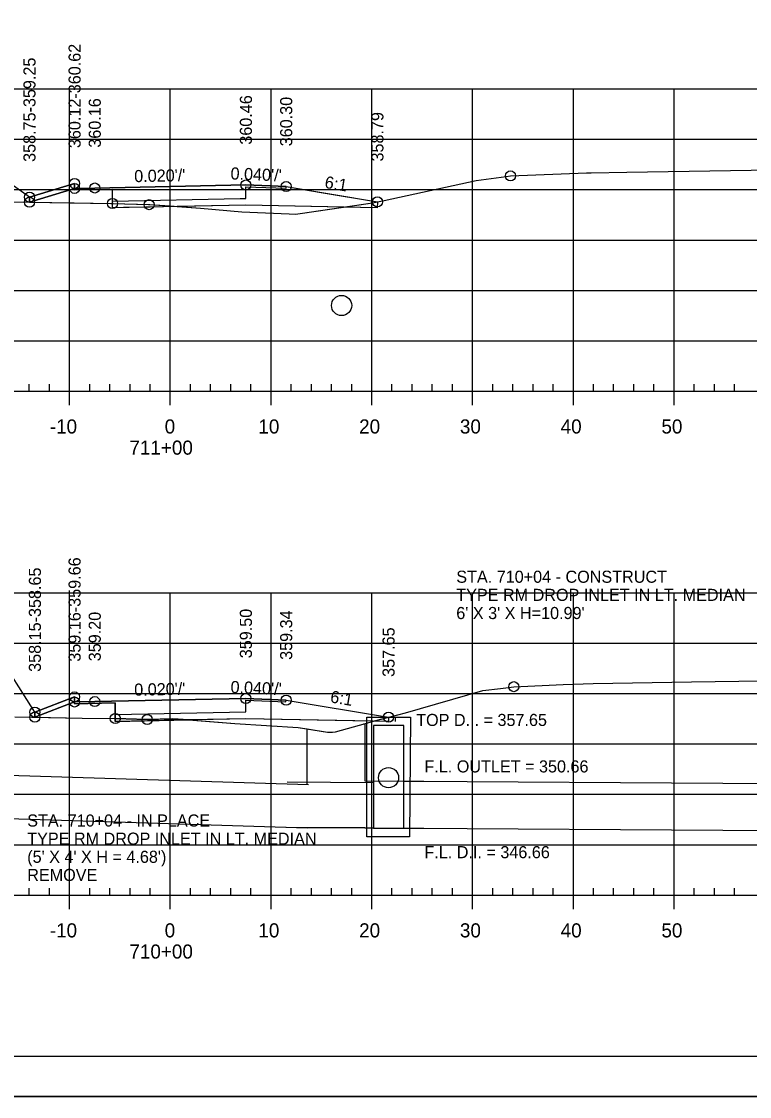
# Model space of a CAD drawing. Extents: x 1359801 to 1362404, y 372415 to 374228.
# Drawn here: x 1361188.9 to 1361261.2, y 373374.6 to 373481.3 of the extents above; entities that cross this region are included whole.
import ezdxf

# ---------------------------------------------------------------- set-up
doc = ezdxf.new("R2010")
doc.units = 0
for name, color, linetype in [('Default', 7, 'Continuous'), ('S_DRG_PT_SYM', 7, 'Continuous'), ('S_ELECTRIC_UTILITIES_ANNOT', 7, 'Continuous'), ('S_IRON_PIN', 7, 'Continuous'), ('S_MAILBOX', 7, 'Continuous'), ('S_PRIMARY_CTL', 7, 'Continuous'), ('S_SANITARY_SEWER', 7, 'Continuous'), ('S_SHOULDER', 7, 'Continuous'), ('S_TELEPHONE_UTILITIES_ANNOT', 7, 'Continuous'), ('S_UNDERGROUND_CABLE', 7, 'Continuous'), ('S_UTILITY_POLE_ANNOT', 7, 'Continuous'), ('S_UTL_PT_SYM', 7, 'Continuous'), ('S_WATER_UTILITIES', 7, 'Continuous')]:
    doc.layers.add(name, color=color, linetype=linetype)

msp = doc.modelspace()

# ---------------------------------------------------------------- linework, layer by layer
at = {"layer": 'Default'}
for points in [[(1361196.21, 373464.76), (1361194.21, 373464.72), (1361194.21, 373465.22), (1361189.73, 373463.85), (1361189.73, 373463.35)], [(1361196.21, 373413.8), (1361194.21, 373413.76), (1361194.21, 373414.26), (1361190.27, 373412.75), (1361190.27, 373412.25)]]:
    msp.add_lwpolyline(points, dxfattribs=at)
at = {"layer": 'S_DRG_PT_SYM'}
for points in [[(1361187.73, 373463.38), (1361197.79, 373463.23), (1361197.97, 373463.23), (1361201.56, 373463.11), (1361201.6, 373463.11), (1361201.67, 373463.11), (1361203.66, 373462.98), (1361206.69, 373462.75), (1361210.8, 373462.41), (1361215.49, 373462.19), (1361216.14, 373462.16), (1361216.61, 373462.23), (1361223.76, 373463.29), (1361224.92, 373463.53), (1361234.05, 373465.49), (1361237.05, 373465.9), (1361237.47, 373465.96), (1361245.01, 373466.27), (1361245.47, 373466.28), (1361249.03, 373466.33), (1361271.64, 373466.69)], [(1361188.27, 373412.28), (1361194.97, 373412.17), (1361198.25, 373412.12), (1361199.34, 373412.09), (1361201.42, 373412.02), (1361203.71, 373412.09), (1361203.97, 373412.1), (1361204.81, 373412.04), (1361210.1, 373411.64), (1361216.4, 373411.23), (1361219.31, 373410.78), (1361219.82, 373410.75), (1361220.09, 373410.81), (1361223.08, 373411.64), (1361224.01, 373411.89), (1361227.06, 373412.69), (1361234.73, 373414.91), (1361236.49, 373415.11), (1361237.79, 373415.28), (1361242.7, 373415.48), (1361245.66, 373415.6), (1361255.44, 373415.75), (1361271.89, 373415.98)]]:
    msp.add_lwpolyline(points, dxfattribs=at)
at = {"layer": 'S_ELECTRIC_UTILITIES_ANNOT'}
for p, q in [((1361189.73, 373463.35), (1361194.21, 373464.72)), ((1361194.21, 373464.72), (1361189.73, 373463.35)), ((1361189.73, 373463.35), (1361194.17, 373463.28)), ((1361197.98, 373463.3), (1361197.96, 373463.3)), ((1361194.21, 373413.59), (1361194.21, 373413.59)), ((1361198.25, 373412.12), (1361198.24, 373412.34)), ((1361198.25, 373412.12), (1361198.24, 373412.34)), ((1361211.21, 373412.1), (1361211.21, 373412.1)), ((1361223.84, 373411.85), (1361223.84, 373411.85)), ((1361223.84, 373411.85), (1361223.84, 373411.85)), ((1361223.84, 373411.85), (1361223.84, 373411.85)), ((1361223.84, 373411.85), (1361223.84, 373411.85))]:
    msp.add_line(p, q, dxfattribs=at)
for points in [[(1361194.17, 373463.28), (1361197.97, 373463.23), (1361197.97, 373464.62), (1361194.21, 373464.55), (1361194.21, 373464.72)], [(1361197.96, 373463.3), (1361197.97, 373463.23), (1361197.98, 373463.22)], [(1361220.9, 373462.87), (1361211.21, 373463.06), (1361204.4, 373462.92)], [(1361204.4, 373462.92), (1361206.69, 373462.75), (1361210.8, 373462.41), (1361215.49, 373462.19), (1361216.14, 373462.16), (1361216.61, 373462.23), (1361220.9, 373462.87)], [(1361190.27, 373412.25), (1361194.21, 373413.76), (1361194.21, 373413.59)], [(1361194.21, 373413.59), (1361194.21, 373413.76), (1361190.27, 373412.25)], [(1361198.24, 373412.34), (1361198.25, 373413.67), (1361194.21, 373413.59)], [(1361190.27, 373412.25), (1361194.97, 373412.17), (1361198.25, 373412.12)], [(1361211.21, 373412.1), (1361205.52, 373411.99), (1361210.1, 373411.64), (1361216.4, 373411.23), (1361217.28, 373411.1), (1361219.31, 373410.78), (1361219.82, 373410.75), (1361220.09, 373410.81), (1361223.08, 373411.64), (1361223.2, 373411.67), (1361223.84, 373411.85)], [(1361223.84, 373411.85), (1361211.21, 373412.1)], [(1361223.84, 373411.85), (1361223.84, 373411.85), (1361223.84, 373411.85)], [(1361223.84, 373411.85), (1361223.84, 373411.85), (1361223.84, 373411.85)]]:
    msp.add_lwpolyline(points, dxfattribs=at)
for points in [[(1361197.98, 373462.8), (1361197.97, 373463.23), (1361201.67, 373463.11), (1361204.4, 373462.92), (1361201.71, 373462.87), (1361199.05, 373462.82)], [(1361220.9, 373462.87), (1361223.76, 373463.29), (1361224.26, 373463.39), (1361224.25, 373462.8)], [(1361198.25, 373412.12), (1361198.25, 373411.84), (1361205.52, 373411.99), (1361203.97, 373412.1), (1361201.42, 373412.02)], [(1361223.84, 373411.85), (1361225.37, 373412.25), (1361225.37, 373411.83)]]:
    msp.add_lwpolyline(points, close=True, dxfattribs=at)
at = {"layer": 'S_MAILBOX'}
for p, q in [((1361058.71, 373474.6), (1361348.71, 373474.6)), ((1361058.71, 373474.6), (1361348.71, 373474.6)), ((1361193.71, 373444.6), (1361193.71, 373474.6)), ((1361193.71, 373444.6), (1361193.71, 373474.6)), ((1361203.71, 373444.6), (1361203.71, 373474.6)), ((1361203.71, 373444.6), (1361203.71, 373474.6)), ((1361213.71, 373444.6), (1361213.71, 373474.6)), ((1361213.71, 373444.6), (1361213.71, 373474.6)), ((1361223.71, 373444.6), (1361223.71, 373474.6)), ((1361223.71, 373444.6), (1361223.71, 373474.6)), ((1361233.71, 373444.6), (1361233.71, 373474.6)), ((1361233.71, 373444.6), (1361233.71, 373474.6)), ((1361243.71, 373444.6), (1361243.71, 373474.6)), ((1361243.71, 373444.6), (1361243.71, 373474.6)), ((1361253.71, 373444.6), (1361253.71, 373474.6)), ((1361253.71, 373444.6), (1361253.71, 373474.6)), ((1361058.71, 373469.6), (1361348.71, 373469.6)), ((1361058.71, 373469.6), (1361348.71, 373469.6)), ((1361058.71, 373464.6), (1361348.71, 373464.6)), ((1361058.71, 373464.6), (1361348.71, 373464.6)), ((1361058.71, 373459.6), (1361348.71, 373459.6)), ((1361058.71, 373459.6), (1361348.71, 373459.6)), ((1361058.71, 373454.6), (1361348.71, 373454.6)), ((1361058.71, 373454.6), (1361348.71, 373454.6)), ((1361058.71, 373449.6), (1361348.71, 373449.6)), ((1361058.71, 373449.6), (1361348.71, 373449.6)), ((1361058.71, 373444.6), (1361348.71, 373444.6)), ((1361058.71, 373444.6), (1361348.71, 373444.6)), ((1361058.71, 373424.6), (1361348.71, 373424.6)), ((1361193.71, 373394.6), (1361193.71, 373424.6)), ((1361203.71, 373394.6), (1361203.71, 373424.6)), ((1361213.71, 373394.6), (1361213.71, 373424.6)), ((1361223.71, 373394.6), (1361223.71, 373424.6)), ((1361233.71, 373394.6), (1361233.71, 373424.6)), ((1361243.71, 373394.6), (1361243.71, 373424.6)), ((1361253.71, 373394.6), (1361253.71, 373424.6)), ((1361058.71, 373419.6), (1361348.71, 373419.6)), ((1361058.71, 373414.6), (1361348.71, 373414.6)), ((1361058.71, 373409.6), (1361348.71, 373409.6)), ((1361058.71, 373404.6), (1361348.71, 373404.6)), ((1361058.71, 373399.6), (1361348.71, 373399.6)), ((1361058.71, 373394.6), (1361348.71, 373394.6))]:
    msp.add_line(p, q, dxfattribs=at)
at = {"layer": 'S_SANITARY_SEWER'}
for points in [[(1361189.73, 373463.35), (1361189.73, 373463.85), (1361194.21, 373465.22), (1361194.21, 373464.72), (1361196.21, 373464.76), (1361211.19, 373465.06), (1361211.21, 373465.06), (1361215.21, 373464.9), (1361215.21, 373464.9), (1361215.22, 373464.9), (1361218.67, 373464.32), (1361224.26, 373463.39)], [(1361215.21, 373464.9), (1361211.21, 373465.06), (1361196.21, 373464.76)], [(1361190.27, 373412.25), (1361190.27, 373412.75), (1361194.21, 373414.26), (1361194.21, 373413.76), (1361196.21, 373413.8), (1361211.21, 373414.1), (1361215.21, 373413.94), (1361225.37, 373412.25)], [(1361215.21, 373413.94), (1361211.21, 373414.1), (1361196.21, 373413.8)]]:
    msp.add_lwpolyline(points, dxfattribs=at)
at = {"layer": 'S_SHOULDER'}
for p, q in [((1361225.37, 373412.25), (1361225.37, 373411.83)), ((1361225.37, 373411.83), (1361225.37, 373411.82)), ((1361226.03, 373412.25), (1361226.03, 373411.83)), ((1361033.31, 373374.62), (1361366.64, 373374.62))]:
    msp.add_line(p, q, dxfattribs=at)
for points in [[(1361033.3, 373587.95), (1361366.64, 373587.95), (1361366.64, 373374.61), (1361033.3, 373374.61)], [(1361279.63, 373584.06), (1361279.63, 373574.18), (1361315.36, 373574.18), (1361315.36, 373571.26), (1361338.56, 373571.26), (1361338.56, 373546.93), (1361361.89, 373546.93), (1361361.89, 373378.6), (1361045.71, 373378.6), (1361045.71, 373584.06)]]:
    msp.add_lwpolyline(points, close=True, dxfattribs=at)
for points in [[(1361197.98, 373463.46), (1361210.63, 373463.71), (1361211.21, 373463.73), (1361211.19, 373464.89)], [(1361211.19, 373464.89), (1361211.21, 373464.89), (1361215.19, 373464.73), (1361215.21, 373464.73)], [(1361215.21, 373464.73), (1361215.21, 373464.9), (1361224.26, 373463.39)], [(1361224.26, 373463.39), (1361224.25, 373462.8), (1361211.21, 373463.06), (1361197.98, 373462.8), (1361197.98, 373463.46)], [(1361198.25, 373412.51), (1361211.21, 373412.77), (1361211.21, 373413.93)], [(1361211.21, 373413.93), (1361215.19, 373413.77), (1361215.21, 373413.94), (1361225.37, 373412.25)], [(1361225.37, 373411.82), (1361211.21, 373412.1), (1361198.25, 373411.84), (1361198.25, 373412.51)]]:
    msp.add_lwpolyline(points, dxfattribs=at)
for centre in [(1361194.21, 373465.22), (1361237.47, 373465.96), (1361194.21, 373464.72), (1361196.21, 373464.76), (1361211.21, 373465.06), (1361215.21, 373464.9), (1361189.73, 373463.85), (1361189.73, 373463.35), (1361197.97, 373463.23), (1361201.6, 373463.11), (1361224.26, 373463.39), (1361237.79, 373415.28), (1361194.21, 373414.26), (1361211.21, 373414.1), (1361215.21, 373413.94), (1361194.21, 373413.76), (1361196.21, 373413.8), (1361190.27, 373412.75), (1361190.27, 373412.25), (1361198.25, 373412.12), (1361201.42, 373412.02), (1361225.37, 373412.25)]:
    msp.add_circle(centre, 0.5, dxfattribs=at)
at = {"layer": 'S_TELEPHONE_UTILITIES_ANNOT'}
for points in [[(1361189.73, 373463.85), (1361180.91, 373470.08), (1361180.91, 373470.08), (1361179.05, 373470.08)], [(1361190.27, 373412.75), (1361178.82, 373430.82), (1361178.82, 373430.82), (1361173.45, 373430.82)]]:
    msp.add_lwpolyline(points, dxfattribs=at)
at = {"layer": 'S_UNDERGROUND_CABLE'}
msp.add_line((1361225.37, 373412.25), (1361225.37, 373411.83), dxfattribs=at)
for points in [[(1361224.26, 373463.39), (1361224.25, 373462.8), (1361211.21, 373463.06), (1361197.98, 373462.8), (1361197.97, 373464.62), (1361194.21, 373464.55), (1361194.21, 373464.72), (1361194.21, 373464.72)], [(1361194.21, 373413.59), (1361198.25, 373413.67), (1361198.25, 373411.84)], [(1361225.37, 373411.82), (1361211.21, 373412.1), (1361198.25, 373411.84), (1361198.25, 373413.67), (1361194.21, 373413.59)]]:
    msp.add_lwpolyline(points, dxfattribs=at)
at = {"layer": 'S_UTILITY_POLE_ANNOT'}
for p, q in [((1361224.52, 373412.25), (1361227.52, 373412.25)), ((1361163.02, 373407.25), (1361217.42, 373405.58)), ((1361223.03, 373405.95), (1361348.74, 373405.14)), ((1361215.32, 373405.84), (1361223.9, 373405.77)), ((1361162.89, 373402.95), (1361217.28, 373401.28)), ((1361215.29, 373401.34), (1361223.87, 373401.27)), ((1361223, 373401.28), (1361348.71, 373400.47)), ((1361226.87, 373401.25), (1361228.87, 373401.24))]:
    msp.add_line(p, q, dxfattribs=at)
for points in [[(1361223, 373411.59), (1361223, 373405.95)], [(1361217.28, 373405.58), (1361217.28, 373411.1)], [(1361226.87, 373405.92), (1361226.87, 373405.92), (1361228.87, 373405.91)], [(1361223, 373401.28), (1361217.28, 373401.28)]]:
    msp.add_lwpolyline(points, dxfattribs=at)
for points in [[(1361223.2, 373412.25), (1361227.54, 373412.25), (1361227.54, 373412.25), (1361227.46, 373400.38), (1361223.2, 373400.38)], [(1361223.87, 373411.42), (1361223.87, 373401.25), (1361226.87, 373401.25), (1361226.87, 373411.42)]]:
    msp.add_lwpolyline(points, close=True, dxfattribs=at)
for centre in [(1361220.71, 373453.1), (1361225.37, 373406.25)]:
    msp.add_circle(centre, 1, dxfattribs=at)
at = {"layer": 'S_UTL_PT_SYM'}
msp.add_line((1361361.89, 373378.6), (1361045.71, 373378.6), dxfattribs=at)
at = {"layer": 'S_WATER_UTILITIES'}
for p, q in [((1361058.71, 373444.6), (1361348.71, 373444.6)), ((1361189.71, 373444.6), (1361189.71, 373445.3)), ((1361191.71, 373444.6), (1361191.71, 373445.3)), ((1361193.71, 373443.2), (1361193.71, 373444.6)), ((1361195.71, 373444.6), (1361195.71, 373445.3)), ((1361197.71, 373444.6), (1361197.71, 373445.3)), ((1361199.71, 373444.6), (1361199.71, 373445.3)), ((1361201.71, 373444.6), (1361201.71, 373445.3)), ((1361203.71, 373443.2), (1361203.71, 373444.6)), ((1361205.71, 373444.6), (1361205.71, 373445.3)), ((1361207.71, 373444.6), (1361207.71, 373445.3)), ((1361209.71, 373444.6), (1361209.71, 373445.3)), ((1361211.71, 373444.6), (1361211.71, 373445.3)), ((1361213.71, 373443.2), (1361213.71, 373444.6)), ((1361215.71, 373444.6), (1361215.71, 373445.3)), ((1361217.71, 373444.6), (1361217.71, 373445.3)), ((1361219.71, 373444.6), (1361219.71, 373445.3)), ((1361221.71, 373444.6), (1361221.71, 373445.3)), ((1361223.71, 373443.2), (1361223.71, 373444.6)), ((1361225.71, 373444.6), (1361225.71, 373445.3)), ((1361227.71, 373444.6), (1361227.71, 373445.3)), ((1361229.71, 373444.6), (1361229.71, 373445.3)), ((1361231.71, 373444.6), (1361231.71, 373445.3)), ((1361233.71, 373443.2), (1361233.71, 373444.6)), ((1361235.71, 373444.6), (1361235.71, 373445.3)), ((1361237.71, 373444.6), (1361237.71, 373445.3)), ((1361239.71, 373444.6), (1361239.71, 373445.3)), ((1361241.71, 373444.6), (1361241.71, 373445.3)), ((1361243.71, 373443.2), (1361243.71, 373444.6)), ((1361245.71, 373444.6), (1361245.71, 373445.3)), ((1361247.71, 373444.6), (1361247.71, 373445.3)), ((1361249.71, 373444.6), (1361249.71, 373445.3)), ((1361251.71, 373444.6), (1361251.71, 373445.3)), ((1361253.71, 373443.2), (1361253.71, 373444.6)), ((1361255.71, 373444.6), (1361255.71, 373445.3)), ((1361257.71, 373444.6), (1361257.71, 373445.3)), ((1361259.71, 373444.6), (1361259.71, 373445.3)), ((1361189.71, 373394.6), (1361189.71, 373395.3)), ((1361191.71, 373394.6), (1361191.71, 373395.3)), ((1361195.71, 373394.6), (1361195.71, 373395.3)), ((1361197.71, 373394.6), (1361197.71, 373395.3)), ((1361199.71, 373394.6), (1361199.71, 373395.3)), ((1361201.71, 373394.6), (1361201.71, 373395.3)), ((1361205.71, 373394.6), (1361205.71, 373395.3)), ((1361207.71, 373394.6), (1361207.71, 373395.3)), ((1361209.71, 373394.6), (1361209.71, 373395.3)), ((1361211.71, 373394.6), (1361211.71, 373395.3)), ((1361215.71, 373394.6), (1361215.71, 373395.3)), ((1361217.71, 373394.6), (1361217.71, 373395.3)), ((1361219.71, 373394.6), (1361219.71, 373395.3)), ((1361221.71, 373394.6), (1361221.71, 373395.3)), ((1361225.71, 373394.6), (1361225.71, 373395.3)), ((1361227.71, 373394.6), (1361227.71, 373395.3)), ((1361229.71, 373394.6), (1361229.71, 373395.3)), ((1361231.71, 373394.6), (1361231.71, 373395.3)), ((1361235.71, 373394.6), (1361235.71, 373395.3)), ((1361237.71, 373394.6), (1361237.71, 373395.3)), ((1361239.71, 373394.6), (1361239.71, 373395.3)), ((1361241.71, 373394.6), (1361241.71, 373395.3)), ((1361245.71, 373394.6), (1361245.71, 373395.3)), ((1361247.71, 373394.6), (1361247.71, 373395.3)), ((1361249.71, 373394.6), (1361249.71, 373395.3)), ((1361251.71, 373394.6), (1361251.71, 373395.3)), ((1361255.71, 373394.6), (1361255.71, 373395.3)), ((1361257.71, 373394.6), (1361257.71, 373395.3)), ((1361259.71, 373394.6), (1361259.71, 373395.3)), ((1361058.71, 373394.6), (1361348.71, 373394.6)), ((1361193.71, 373393.2), (1361193.71, 373394.6)), ((1361203.71, 373393.2), (1361203.71, 373394.6)), ((1361213.71, 373393.2), (1361213.71, 373394.6)), ((1361223.71, 373393.2), (1361223.71, 373394.6)), ((1361233.71, 373393.2), (1361233.71, 373394.6)), ((1361243.71, 373393.2), (1361243.71, 373394.6)), ((1361253.71, 373393.2), (1361253.71, 373394.6))]:
    msp.add_line(p, q, dxfattribs=at)

# ---------------------------------------------------------------- texts
at = {"layer": 'S_IRON_PIN'}
for s, rotation, p in [('360.12-360.62', 90, (1361194.81, 373468.72)), ('358.75-359.25', 90, (1361190.33, 373467.35)), ('360.16', 90, (1361196.81, 373468.76)), ('360.46', 90, (1361211.81, 373469.06)), ('360.30', 90, (1361215.81, 373468.9)), ('358.79', 90, (1361224.86, 373467.39)), ("0.020'/'", 1.1458, (1361200.14, 373465.34)), ("0.040'/'", 357.7097, (1361209.67, 373465.62)), ('6:1', 350.5354, (1361218.97, 373464.78)), ('359.16-359.66', 90, (1361194.81, 373417.76)), ('358.15-358.65', 90, (1361190.87, 373416.75)), ('359.50', 90, (1361211.81, 373418.1)), ('359.20', 90, (1361196.81, 373417.8)), ('359.34', 90, (1361215.81, 373417.94)), ('357.65', 90, (1361225.97, 373416.25)), ("0.020'/'", 1.1458, (1361200.14, 373414.38)), ("0.040'/'", 357.7098, (1361209.67, 373414.66)), ('6:1', 350.5401, (1361219.52, 373413.73))]:
    msp.add_text(s, height=1.2, rotation=rotation, dxfattribs=at).set_placement(p)
at = {"layer": 'S_PRIMARY_CTL'}
for s, p in [('-10', (1361191.75, 373440.4)), ('0', (1361203.15, 373440.4)), ('10', (1361212.45, 373440.4)), ('20', (1361222.45, 373440.4)), ('30', (1361232.45, 373440.4)), ('40', (1361242.45, 373440.4)), ('50', (1361252.45, 373440.4)), ('711+00', (1361199.65, 373438.3)), ('-10', (1361191.75, 373390.4)), ('0', (1361203.15, 373390.4)), ('10', (1361212.45, 373390.4)), ('20', (1361222.45, 373390.4)), ('30', (1361232.45, 373390.4)), ('40', (1361242.45, 373390.4)), ('50', (1361252.45, 373390.4)), ('710+00', (1361199.65, 373388.3))]:
    msp.add_text(s, height=1.4, dxfattribs=at).set_placement(p)
at = {"layer": 'S_SHOULDER'}
for p in [(1361245.43, 373466.23), (1361245.62, 373415.55), (1361217.24, 373411.13), (1361222.85, 373411.58), (1361222.85, 373411.58), (1361222.96, 373411.54), (1361217.24, 373411.1)]:
    msp.add_text('+', height=0.1, dxfattribs=at).set_placement(p)
at = {"layer": 'S_UTILITY_POLE_ANNOT'}
for s, p in [('STA. 710+04 - CONSTRUCT', (1361232.09, 373425.59)), ('TYPE RM DROP INLET IN LT. MEDIAN', (1361232.09, 373423.79)), ("6' X 3' X H=10.99'", (1361232.09, 373421.99)), ('TOP D.I. = 357.65', (1361228.11, 373411.38)), ('F.L. OUTLET = 350.66', (1361228.93, 373406.77)), ('STA. 710+04 - IN PLACE', (1361189.51, 373401.4)), ('TYPE RM DROP INLET IN LT. MEDIAN', (1361189.51, 373399.6)), ('F.L. D.I. = 346.66', (1361228.93, 373398.26)), ("(5' X 4' X H = 4.68')", (1361189.51, 373397.8)), ('REMOVE', (1361189.51, 373396))]:
    msp.add_text(s, height=1.2, dxfattribs=at).set_placement(p)

doc.saveas('drawing.dxf')
